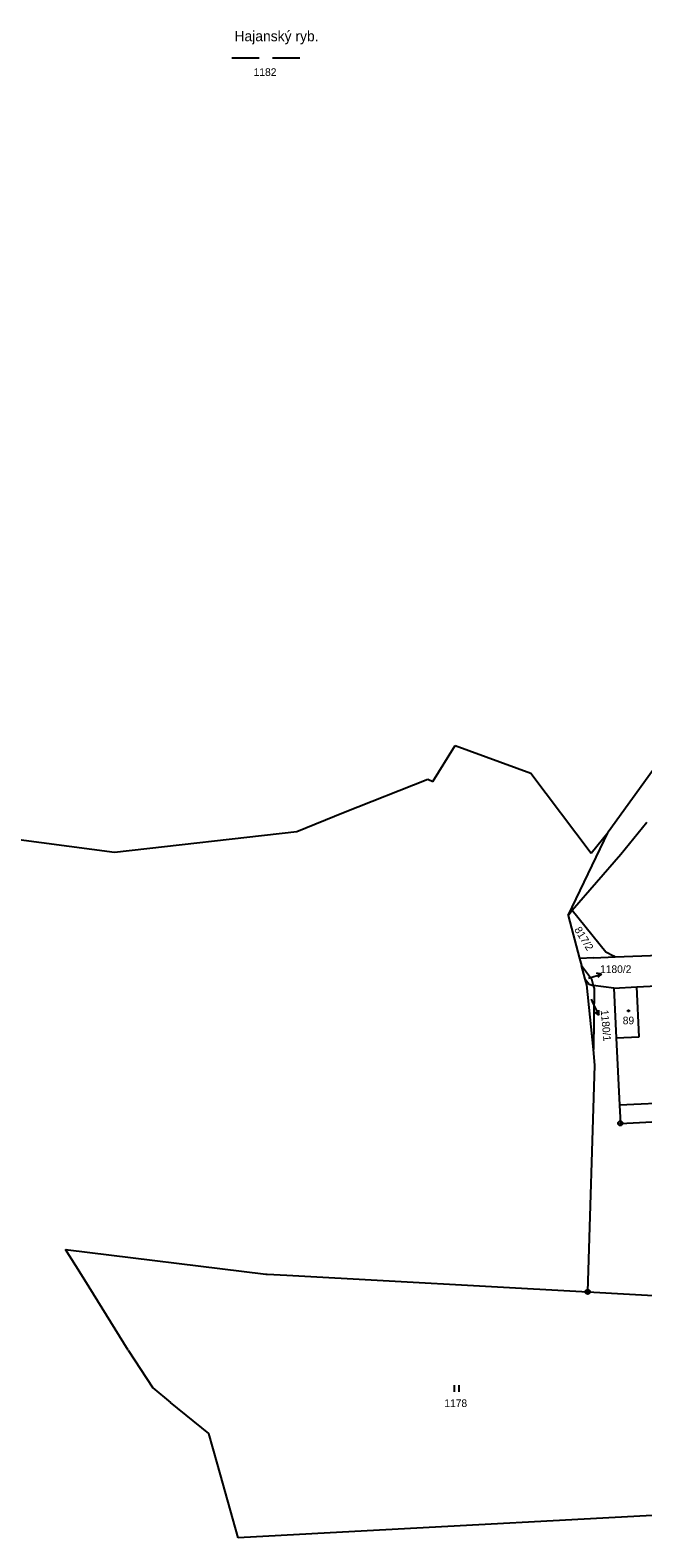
# Model space of a CAD drawing. Extents: x -796130 to -793145, y -1109506 to -1106267.
# Drawn here: x -793552.6 to -793416.9, y -1109283.2 to -1108949.2 of the extents above; entities that cross this region are included whole.
import ezdxf

# ---------------------------------------------------------------- set-up
doc = ezdxf.new("R2010")
doc.units = 0
for name, color, linetype in [('Komunikace', 7, 'Continuous'), ('Vrstva 1', 7, 'Continuous'), ('Vrstva 14', 7, 'Continuous'), ('Vrstva 15', 7, 'Continuous'), ('Vrstva 16', 7, 'Continuous'), ('Vrstva 23', 7, 'Continuous'), ('Vrstva 25', 7, 'Continuous'), ('Vrstva 28', 7, 'Continuous'), ('Vrstva 4', 7, 'Continuous'), ('Vrstva 44', 7, 'Continuous')]:
    doc.layers.add(name, color=color, linetype=linetype)

msp = doc.modelspace()

# ---------------------------------------------------------------- linework, layer by layer
at = {"layer": 'Komunikace'}
for p, q in [((-793428.95, -1109159.2), (-793428.93, -1109159.2)), ((-793428.34, -1109163.89), (-793427.93, -1109164.74))]:
    msp.add_line(p, q, dxfattribs=at)
at = {"layer": 'Vrstva 1'}
for p, q in [((-793413.79, -1109111.98), (-793424.54, -1109126.87)), ((-793421.73, -1109131.74), (-793415.97, -1109124.66)), ((-793432.5, -1109144.19), (-793421.73, -1109131.74)), ((-793433.42, -1109145.32), (-793432.5, -1109144.19)), ((-793427.74, -1109154.69), (-793430.88, -1109154.83)), ((-793427.74, -1109154.69), (-793422.98, -1109154.5)), ((-793422.98, -1109154.5), (-793407.89, -1109153.9)), ((-793430.45, -1109156.44), (-793428.26, -1109159.35)), ((-793428.26, -1109159.35), (-793427.87, -1109160.85)), ((-793427.87, -1109160.85), (-793427.69, -1109161.51)), ((-793423.31, -1109161.43), (-793427.87, -1109160.85)), ((-793427.69, -1109161.51), (-793427.84, -1109175)), ((-793423.31, -1109161.43), (-793418.21, -1109161.13)), ((-793423.31, -1109161.43), (-793422.78, -1109172.46)), ((-793418.21, -1109161.13), (-793391.08, -1109159.72)), ((-793417.72, -1109172.22), (-793418.21, -1109161.13)), ((-793422.78, -1109172.46), (-793417.72, -1109172.22)), ((-793422.78, -1109172.46), (-793422.06, -1109187.38)), ((-793390.08, -1109185.79), (-793422.06, -1109187.38)), ((-793422.06, -1109187.38), (-793421.86, -1109191.38)), ((-793421.86, -1109191.38), (-793387.93, -1109189.68)), ((-793429.1, -1109228.7), (-793384.16, -1109231.17))]:
    msp.add_line(p, q, dxfattribs=at)
for points in [[(-793432.5, -1109144.19), (-793425.08, -1109153.41), (-793423.39, -1109154.29), (-793422.98, -1109154.5)], [(-793429.64, -1109159.45), (-793428.78, -1109160.54), (-793427.87, -1109160.85)]]:
    msp.add_lwpolyline(points, dxfattribs=at)
at = {"layer": 'Vrstva 16'}
for p, q in [((-793428.93, -1109159.2), (-793426.065, -1109158.307)), ((-793426.065, -1109158.307), (-793427.169, -1109158.127)), ((-793426.065, -1109158.307), (-793426.871, -1109159.082)), ((-793427.93, -1109164.74), (-793426.632, -1109167.444)), ((-793426.632, -1109167.444), (-793427.515, -1109166.759)), ((-793426.632, -1109167.444), (-793426.614, -1109166.326))]:
    msp.add_line(p, q, dxfattribs=at)
at = {"layer": 'Vrstva 23'}
for p, q in [((-793507.92, -1108955.31), (-793501.92, -1108955.31)), ((-793498.92, -1108955.31), (-793492.92, -1108955.31)), ((-793458.64, -1109250.88), (-793458.64, -1109249.38)), ((-793457.64, -1109249.38), (-793457.64, -1109250.88))]:
    msp.add_line(p, q, dxfattribs=at)
at = {"layer": 'Vrstva 25'}
for p, q in [((-793420.2, -1109166.32), (-793419.9, -1109166.32)), ((-793420.2, -1109166.62), (-793420.2, -1109166.32)), ((-793419.9, -1109166.62), (-793420.2, -1109166.62)), ((-793419.9, -1109166.32), (-793419.9, -1109166.62))]:
    msp.add_line(p, q, dxfattribs=at)
at = {"layer": 'Vrstva 28'}
for centre, radius in [((-793421.86, -1109191.38), 0.5), ((-793421.86, -1109191.38), 0.01), ((-793429.1, -1109228.7), 0.5), ((-793429.1, -1109228.7), 0.01)]:
    msp.add_circle(centre, radius, dxfattribs=at)
at = {"layer": 'Vrstva 4'}
for p, q in [((-793463.38, -1109115.64), (-793458.44, -1109107.69)), ((-793458.44, -1109107.69), (-793441.68, -1109113.78)), ((-793483.2, -1109122.55), (-793464.5, -1109115.1)), ((-793464.5, -1109115.1), (-793463.38, -1109115.64)), ((-793441.68, -1109113.78), (-793428.33, -1109131.56)), ((-793493.53, -1109126.7), (-793483.2, -1109122.55)), ((-793571.85, -1109126.33), (-793533.97, -1109131.3)), ((-793533.97, -1109131.3), (-793493.53, -1109126.7)), ((-793433.42, -1109145.32), (-793424.54, -1109126.87)), ((-793428.33, -1109131.56), (-793424.54, -1109126.87)), ((-793433.42, -1109145.32), (-793430.88, -1109154.83)), ((-793430.88, -1109154.83), (-793430.45, -1109156.44)), ((-793429.64, -1109159.45), (-793430.45, -1109156.44)), ((-793429.32, -1109160.66), (-793429.64, -1109159.45)), ((-793427.84, -1109175), (-793429.32, -1109160.66)), ((-793427.5, -1109178.5), (-793427.84, -1109175)), ((-793429.1, -1109228.7), (-793427.5, -1109178.5)), ((-793544.81, -1109219.32), (-793500.4, -1109224.79)), ((-793542.53, -1109222.97), (-793544.81, -1109219.32)), ((-793540.54, -1109226.15), (-793542.53, -1109222.97)), ((-793530.89, -1109241.59), (-793540.54, -1109226.15)), ((-793500.4, -1109224.79), (-793500.1, -1109224.8)), ((-793500.1, -1109224.8), (-793495.74, -1109225.04)), ((-793495.74, -1109225.04), (-793429.1, -1109228.7)), ((-793530.89, -1109241.59), (-793525.49, -1109249.99)), ((-793525.49, -1109249.99), (-793521.54, -1109253.19)), ((-793513.04, -1109260.05), (-793521.54, -1109253.19)), ((-793511.13, -1109266.85), (-793513.04, -1109260.05)), ((-793506.53, -1109283.2), (-793511.13, -1109266.85)), ((-793404.49, -1109277.73), (-793480.71, -1109281.82)), ((-793480.71, -1109281.82), (-793506.53, -1109283.2))]:
    msp.add_line(p, q, dxfattribs=at)

# ---------------------------------------------------------------- texts
at = {"layer": 'Vrstva 14'}
for s, height, p in [('1182', 1.7, (-793503.123, -1108959.35)), ('1180/2', 0.1, (-793429.17, -1109159.2)), ('1180/1', 0.1, (-793428.547, -1109163.89)), ('1178', 1.7, (-793460.869, -1109254.23))]:
    msp.add_text(s, height=height, dxfattribs=at).set_placement(p)
msp.add_text('817/2', height=1.7, rotation=301.5189, dxfattribs=at).set_placement((-793432.134, -1109148.464))
at = {"layer": 'Vrstva 15'}
msp.add_text('89', height=1.7, dxfattribs=at).set_placement((-793421.33, -1109169.44))
at = {"layer": 'Vrstva 16'}
msp.add_text('1180/2', height=1.7, dxfattribs=at).set_placement((-793426.365, -1109158.08))
msp.add_text('1180/1', height=1.7, rotation=275.11155, dxfattribs=at).set_placement((-793426.213, -1109166.315))
at = {"layer": 'Vrstva 44'}
msp.add_text('Hajanský ryb.', height=2.3, dxfattribs=at).set_placement((-793507.37, -1108951.67))

doc.saveas('drawing.dxf')
